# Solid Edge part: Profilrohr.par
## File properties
Username: bmolnar
Dokumentum tartalom típus: 0
Author: bmolnar
Last saved by: bmolnar
Revision: 81
Sűrűség: 0,000 kg/m^3
Pontosság: 0,990
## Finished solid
Body 1: solid body, 115 faces, 338 edges, 224 vertices.
  Faces by surface: cylinder 59, plane 56
  Edges by curve: line 220, circle 118
Bounding box of the edges (mm): 77.000 x 77.000 x 51.500, from (-38.5, -38.5, 0) to (38.5, 38.5, 51.5).
Cylindrical faces by radius (mm): R0.15 x24, R0.25 x24, R1 x4, R12 x4, R13.5 x2, R31.5 x1
Planar faces by outward normal: +x 13, +y 14, +z 1, -x 13, -y 14, -z 1
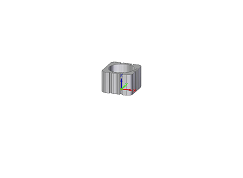
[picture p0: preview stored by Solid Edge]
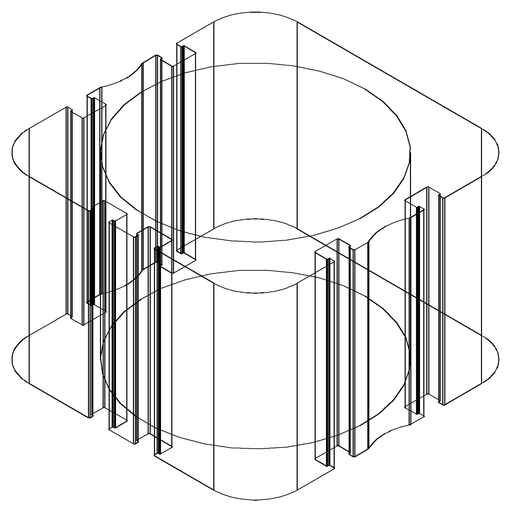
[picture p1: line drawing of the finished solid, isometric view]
